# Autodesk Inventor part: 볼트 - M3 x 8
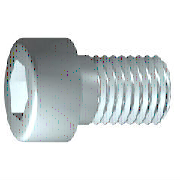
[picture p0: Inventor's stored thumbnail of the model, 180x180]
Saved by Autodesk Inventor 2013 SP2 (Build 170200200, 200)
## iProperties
IsCustomPart: 0
Created: 2012-02
Part Number: 볼트 - M3 x 8
Material: 스테인리스강
Description: 6각 소켓 머리 캡 나사
Document SubType Name: Modeling
Standard: ISO 4762
Designer: mduedu
Standard Revision: Fourth edition 2004-03-01
Standards Organization: ISO
Language: ko-KR
Size Designation: M3 x 8
Categories: <MemberInstance><Categories><Category DisplayName="조임쇠" InternalName="e4da775c-781d-43d5-af7c-5136215cf5a6" Mnemonic="FSTN"><Category DisplayName="볼트" InternalN
Density: 8.08 g/cm^3
Mass: 0.955869 g
Surface Area: 1.83001 cm^2
Volume: 0.118301 cm^3
Author: mduedu
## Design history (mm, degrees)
sketch "스케치1"
  geometry: L1 (-0.867, 0)-(8, 0); L2 (8, 0)-(8, 1.5); L3 (8, 1.5)-(1.25, 1.5); L4 (1.25, 1.5)-(0.943, 1.5); L5 (0.943, 1.5)-(0, 1.5); L6 (0, 1.5)-(0, 2.75); L7 (0, 2.75)-(-3, 2.75); L8 (-3, 2.75)-(-3, 1.443); L9 (-3, 1.443)-(-1.7, 1.443); L10 (-1.7, 1.443)-(-0.867, 0); L11 (-5.2, 0)-(10.2, 0) reference; L12 (0, -0.55)-(0, 3.3) reference; L13 (1.25, 1.5)-(0, 1.5)
  constraints: 22 end point, 6 parallel, 2 collinear, 2 perpendicular, 1 horizontal, 1 point on line
  dimensions: "d1" = 6.75 distance from line of L3.end L2 (= GEL); "d2" = 0.30683 distance of L4.end L3.end (computed from GAL); "d3" = 3 distance between parallel lines of L8 L6 (= KOH); "d4" = 1.3 distance of L8.end L9.end (= INTI); "d5" = 60 deg angle of L10 L1; "d6" = 3 diameter of L3 L1 (= GD); "d7" = 3 diameter of L5 L1 (= BDM); "d8" = 2.88675 diameter of L9 L1 (= 1.1547 x SW); "d9" = 5.5 diameter of L7 L1 (= KOD); "d26" = 8 distance between parallel lines of L12 L2 (= NLG)
revolve "본체" sketch "스케치1" stored, may be unused: angle "d10" = 90 deg
sketch "스케치2"
  geometry: L1 (0, -3.85)-(0, 3.85) reference; L2 (-3.85, 0)-(3.85, 0) reference; L3 (1.443, 0)-(0.722, -1.25); L4 (0.722, -1.25)-(-0.722, -1.25); L5 (-0.722, -1.25)-(-1.443, 0); L6 (-1.443, 0)-(-0.722, 1.25); L7 (-0.722, 1.25)-(0.722, 1.25); L8 (0.722, 1.25)-(1.443, 0); 2 further points
  constraints: 12 end point, 1 coincident, 1 horizontal alignment, 1 point on line, 12 other
extrude "슬롯" join sketch "스케치2" stored distance "d11" = 10; taper "d12" = 0 deg
workplane "Work Plane1"
fillet "Fillet2" dims "d30" = 0.1 (= R)
body "Solid1"
fillet "모깎기1" dims "d17" = 0.3 (= RR)
feature "스레드" dims "d13" = 6.75 (= GEL), "d14" = 0
chamfer "모따기1" distance "d15" = 0.30673 (= -0.5 x SPD + 0.5 x GD); stored, may be unused: second distance "d16" = 0.30673 (= GUL), angle "d27" = 45 deg
other parameters: "GD" = 3 [user parameter; used in 2 equation terms], "NLG" = 8 [user parameter; used in 1 equation term], "GEL" = 6.75 [user parameter; used in 2 equation terms], "KOD" = 5.5 [user parameter; used in 1 equation term], "KOH" = 3 [user parameter; used in 1 equation term], "INTI" = 1.3 [user parameter; used in 1 equation term], "GAL" = 0.30673 (= 0.61345 x PTC) [user parameter; used in 1 equation term], "GUL" = 0.30673 (= 0.61345 x PTC) [user parameter; used in 1 equation term], "BDM" = 3 (= NND) [user parameter; used in 1 equation term], "SW" = 2.5 [user parameter; used in 2 equation terms], "RR" = 0.3 [user parameter; used in 1 equation term], "SPD" = 2.38655 (= NND - 1.2269 x PTC) [user parameter; used in 1 equation term], "d19" = 0, "d28" = 0, "d29" = 0, "R" = 0.1 [user parameter; used in 1 equation term], "TOA" = 30 deg [user parameter], "GD1" = 2.38655 (= THREADDIA - 1.2269 x PTC) [user parameter], "THREADDIA" = 3 [user parameter; used in 1 equation term], "FAWI" = 45 deg [user parameter], "PTC" = 0.5 [user parameter; used in 5 equation terms], "NND" = 3 [user parameter; used in 2 equation terms], "E0" = 2.8875 (= 1.155 x SW) [user parameter]
